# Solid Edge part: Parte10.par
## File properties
Author: f_grande
Template: Normal.par
Last saved by: f_grande
Revision: 10
Application: Solid Edge
Densità: 750,000 kg/m^3
Precisione: 0,99
Tipo di contenuto documento: 0
Material: MDF
Stile della faccia: Marroncino
Coef. of Thermal Exp: 0.0
Thermal Conductivity: 0.0
Specific Heat: 0.0
Modulus of Elasticity: 0.0
Poisson's Ratio: 0.0
Yield Stress: 0.0
Ultimate Stress: 0.0
Elongation: 0.0
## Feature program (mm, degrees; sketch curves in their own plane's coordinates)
sketch for "unnamed Protrusion 1" plane through (0, 0, 0) normal (0, -1, 0) x-axis (1, 0, 0)
  line (-75, 9.5) -> (75, 9.5)
  line (75, 9.5) -> (75, -9.5)
  line (75, -9.5) -> (-75, -9.5)
  line (-75, -9.5) -> (-75, 9.5)
  dimension (linear) = 75
  dimension (linear) = 75
extrude "unnamed Protrusion 1" add finite 125 symmetric
sketch for "ExtrudedCutout_1" plane through (0, -62.5, 9.5) normal (0, 0, 1) x-axis (0, 1, 0)
  circle centre (62.5, 34.35) radius 25
extrude "ExtrudedCutout_1" cut finite 61.365 along -normal
fillet "Rotondo_1" radius 20
sketch for "ExtrudedCutout_3" plane through (0, 0, 9.5) normal (0, 0, 1) x-axis (1, 0, 0)
extrude "ExtrudedCutout_3" cut finite 135 along -normal
sketch for "ExtrudedCutout_4" plane through (0, 0, 9.5) normal (0, 0, 1) x-axis (1, 0, 0)
extrude "ExtrudedCutout_4" cut finite 15 along -normal
sketch for "ExtrudedCutout_5" plane through (0, 0, 9.5) normal (0, 0, 1) x-axis (0, 1, 0)
extrude "ExtrudedCutout_5" cut finite 135 along -normal
sketch for "ExtrudedCutout_6" plane through (-10.25, 0, 9.5) normal (0, 0, 1) x-axis (0, 1, 0)
  circle centre (-62.5, 14.8259) radius 8
extrude "ExtrudedCutout_6" cut finite 120.0938 along -normal
fillet "Rotondo_2" radius 10
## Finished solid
Body 1: solid body, 27 faces, 71 edges, 46 vertices.
  Faces by surface: plane 20, cylinder 7
  Edges by curve: line 57, circle 14
Bounding box of the edges (mm): 129.500 x 125.000 x 19.000, from (-75, -62.5, -9.5) to (54.5, 62.5, 9.5).
Cylindrical faces by radius (mm): R8 x1, R10 x5, R25 x1
Planar faces by outward normal: +x 5, +y 4, +z 2, -x 3, -y 5, -z 1
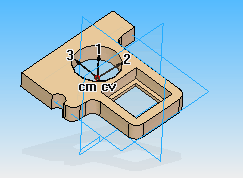
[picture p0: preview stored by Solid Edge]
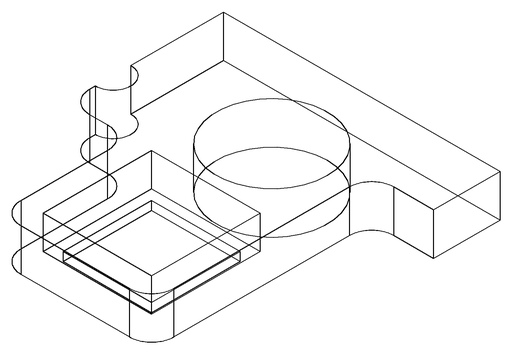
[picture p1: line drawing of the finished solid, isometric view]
